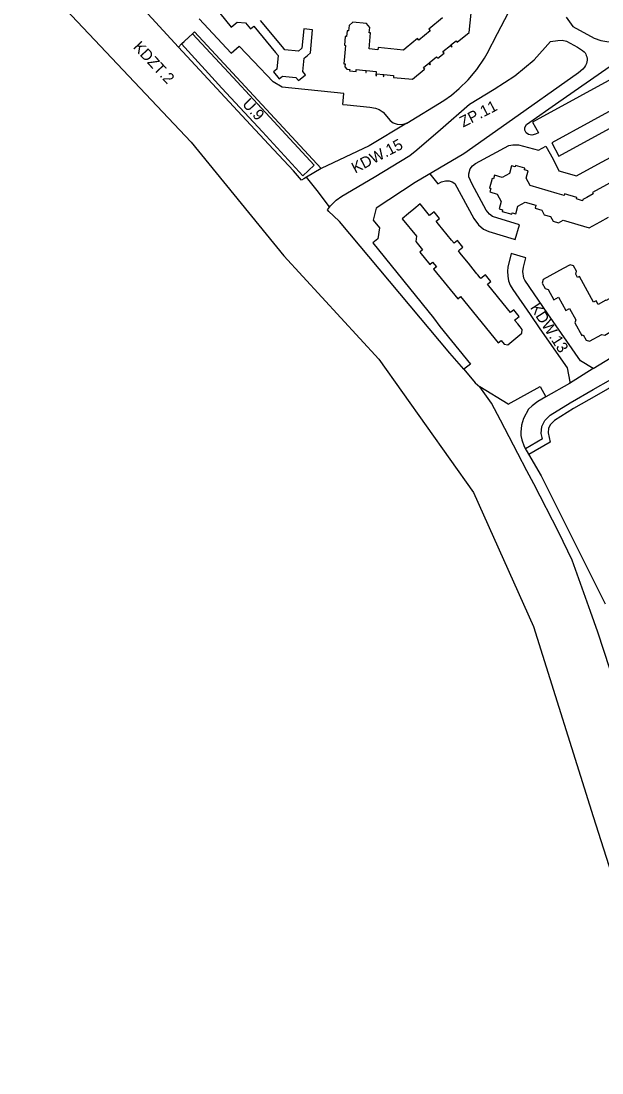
# Model space of a CAD drawing. Extents: x 7426178 to 7427732, y 5548847 to 5550287.
# Drawn here: x 7426699.7 to 7426935.7, y 5549279.8 to 5549707.1 of the extents above; entities that cross this region are included whole.
import ezdxf

# ---------------------------------------------------------------- set-up
doc = ezdxf.new("R2010")
doc.units = 0
for name, color, linetype in [('linie_rozgraniczajace', 7, 'Continuous'), ('linie_zabudowy_nieprzekraczalne', 7, 'Continuous'), ('linie_zabudowy_obowiazujace', 7, 'Continuous'), ('oznaczenia_przeznaczen', 7, 'Continuous')]:
    doc.layers.add(name, color=color, linetype=linetype)

msp = doc.modelspace()

# ---------------------------------------------------------------- linework, layer by layer
at = {"layer": 'linie_rozgraniczajace'}
for p, q in [((7426932.15, 5549565.9), (7426922.5, 5549559.91)), ((7426884.2, 5549560.11), (7426886.06, 5549558.53)), ((7426897.6, 5549551.53), (7426886.06, 5549558.53)), ((7426901.49, 5549531.49), (7426894.43, 5549544.99)), ((7426911.56, 5549537.38), (7426904.58, 5549533.3))]:
    msp.add_line(p, q, dxfattribs=at)
for points in [[(7426376.27, 5550136.98), (7426418.26, 5550074.28), (7426423.32, 5550066.18), (7426432.5, 5550051.32), (7426442.7, 5550038.38), (7426480.49, 5549982.45), (7426537.39, 5549902.3), (7426546.67, 5549891.59), (7426553.32, 5549883.92), (7426562.25, 5549871.78), (7426591.41, 5549843), (7426644.02, 5549790.07), (7426768.78, 5549657.84), (7426806.41, 5549611.72)], [(7426810.33, 5549646.2), (7426800.44, 5549656.88), (7426791.22, 5549666.83), (7426763.7, 5549696.53), (7426746.59, 5549715), (7426724.9, 5549738.06), (7426706.19, 5549757.95)], [(7426921.19, 5549708.68), (7426923.92, 5549704.82), (7426932.51, 5549700.17), (7426935.18, 5549699.15), (7426937.7, 5549698.72), (7426940.53, 5549698.67), (7426942.25, 5549698.99), (7426944.97, 5549699.87), (7426946.33, 5549700.48), (7426947.4, 5549701.24), (7426955.49, 5549706.64), (7426958.19, 5549707.88), (7426961.05, 5549708.75), (7426963.27, 5549709.23), (7426965.77, 5549709.6), (7426974.88, 5549710.13), (7426996.27, 5549711.61), (7427000.22, 5549712.16), (7427006.34, 5549713.7), (7427091.63, 5549747.86), (7427113.84, 5549707.59), (7427113.65, 5549702.41), (7427125.67, 5549680.75), (7427127, 5549680.04)], [(7426889.1, 5549693.95), (7426893.27, 5549702.02), (7426902.25, 5549719.14)], [(7426772.11, 5549707.95), (7426785.12, 5549693.98), (7426788.38, 5549696.87)], [(7426763.7, 5549696.53), (7426764.94, 5549697.75), (7426766.01, 5549698.76), (7426769.45, 5549701.97), (7426770.19, 5549702.65), (7426821.62, 5549647.18), (7426815.68, 5549643.69), (7426814.56, 5549643.04), (7426813.58, 5549642.48)], [(7426914.79, 5549698.8), (7426917.74, 5549699.2), (7426919.47, 5549699.28), (7426921.22, 5549698.93), (7426925.81, 5549696.44), (7426927.82, 5549695.15), (7426928.41, 5549694.63), (7426928.81, 5549694.12), (7426929.08, 5549693.66), (7426929.33, 5549693.03), (7426929.5, 5549692.47), (7426929.67, 5549691.91), (7426929.62, 5549691.19), (7426929.57, 5549690.49), (7426929.41, 5549689.78), (7426929.05, 5549689.04), (7426928.63, 5549688.35), (7426927.96, 5549687.56), (7426926.13, 5549686.04), (7426896.99, 5549665.4), (7426879.58, 5549653.14), (7426859.82, 5549641.56), (7426844.02, 5549631.06), (7426842.79, 5549626.24), (7426845.34, 5549623.14), (7426844.65, 5549618.61), (7426842.65, 5549616.98), (7426867.3, 5549586.48), (7426869.83, 5549582.97), (7426882.23, 5549567.76), (7426879.56, 5549565.69), (7426884.2, 5549560.11)], [(7426802.18, 5549682.43), (7426794.17, 5549690.79), (7426788.38, 5549696.87)], [(7426879.56, 5549565.69), (7426873.94, 5549572.19), (7426829.14, 5549625.63), (7426826.68, 5549627.91), (7426824.71, 5549629.72), (7426824.15, 5549630.36), (7426825.38, 5549632.06), (7426827.74, 5549634.28), (7426830.06, 5549635.9), (7426843.16, 5549643.7), (7426857.6, 5549652.43), (7426860.55, 5549654.73), (7426870.08, 5549663.09), (7426881.88, 5549673.34), (7426891.96, 5549679.36), (7426900.35, 5549684.81), (7426908.09, 5549691.28), (7426914.79, 5549698.8)], [(7426871.41, 5549674.74), (7426874.57, 5549677.02), (7426877.72, 5549679.65), (7426881.33, 5549683.25), (7426884.86, 5549687.46), (7426887.93, 5549692.01), (7426889.1, 5549693.95)], [(7426830.37, 5549673.21), (7426830.81, 5549677.61), (7426805.78, 5549680.15), (7426802.18, 5549682.43)], [(7426849.66, 5549666.68), (7426850.81, 5549665.74), (7426852.44, 5549665.25), (7426854.22, 5549665.09), (7426856.43, 5549665.63), (7426871.41, 5549674.74)], [(7426830.37, 5549673.21), (7426832.14, 5549673.01), (7426841.42, 5549672.16), (7426843.75, 5549671.69), (7426845.24, 5549671.14), (7426846.82, 5549670.11), (7426849.66, 5549666.68)], [(7426856.43, 5549665.63), (7426841.11, 5549656.34), (7426821.62, 5549647.18)], [(7426865.76, 5549645.04), (7426869.05, 5549640.99), (7426870.55, 5549641.83), (7426872.2, 5549642.22), (7426873.59, 5549642.16), (7426874.89, 5549641.77), (7426875.93, 5549641.1), (7426883.66, 5549626.91), (7426885.48, 5549624.35), (7426887.62, 5549622.57), (7426889.73, 5549621.59), (7426900, 5549618.51), (7426900.46, 5549618.35), (7426902.13, 5549624.24), (7426891.21, 5549627.63), (7426890.05, 5549628.57), (7426888.71, 5549630.2), (7426882.99, 5549640.88), (7426881.67, 5549643.74), (7426881.58, 5549644.99), (7426882.19, 5549647.11), (7426883.08, 5549648.21), (7426884.33, 5549649.16), (7426897.91, 5549656.55), (7426899.49, 5549656.86), (7426901.81, 5549656.76), (7426909.87, 5549654.57), (7426912.9, 5549656.26), (7426915.84, 5549651), (7426918.12, 5549646.19), (7426925.31, 5549644.17), (7426934.07, 5549648.97), (7426965.67, 5549666.05)], [(7426813.58, 5549642.48), (7426810.33, 5549646.2)], [(7426825.05, 5549631.61), (7426819.94, 5549638.19), (7426815.68, 5549643.69)], [(7426806.41, 5549611.72), (7426845.02, 5549569.73), (7426883.5, 5549515.53), (7426907.93, 5549461.17), (7426932.17, 5549384.03), (7426948.93, 5549331.51), (7426962.26, 5549289.73), (7427024.27, 5549067.18), (7427061.13, 5549001.37), (7427073.43, 5548973.27), (7427176.69, 5548896.63), (7427213.08, 5548849.03)], [(7426932.15, 5549565.9), (7426926.98, 5549569.13), (7426913.7, 5549588.22), (7426904.31, 5549601.79), (7426903.92, 5549602.7), (7426903.5, 5549605.35), (7426903.76, 5549607.11), (7426904.81, 5549610.9), (7426898.83, 5549612.62), (7426897.45, 5549607.09), (7426897.32, 5549605.53), (7426897.48, 5549603.52), (7426897.78, 5549601.57), (7426898.37, 5549599.85), (7426899.43, 5549598.05), (7426906.54, 5549587.93), (7426910.4, 5549582.02), (7426921.61, 5549566.16), (7426922.58, 5549560.57)], [(7426932.15, 5549565.9), (7426941.86, 5549571.96), (7426967.18, 5549586.1), (7426997, 5549602.57)], [(7426911.56, 5549537.38), (7426911.05, 5549539.62), (7426911.32, 5549542.39), (7426912.47, 5549544.85), (7426914.67, 5549546.95), (7426922.71, 5549552.03), (7426932.12, 5549557.37), (7426946.41, 5549565.6)], [(7426894.43, 5549544.99), (7426890.85, 5549551.84), (7426886.06, 5549558.53)], [(7426897.6, 5549551.53), (7426910.58, 5549558.63), (7426912.86, 5549554.47)], [(7426922.58, 5549560.57), (7426922.5, 5549559.91), (7426912.86, 5549554.47), (7426909.67, 5549552.53), (7426907.35, 5549550.78), (7426905.89, 5549549.42), (7426903.87, 5549545.6), (7426902.97, 5549542.93), (7426902.69, 5549540.15), (7426902.78, 5549538.71), (7426903.12, 5549536.97), (7426904.11, 5549534.22), (7426904.88, 5549532.73)], [(7426904.88, 5549532.73), (7426911.01, 5549522.31), (7426916.04, 5549512.37), (7426937.03, 5549470.34)], [(7426931, 5549467.22), (7426923.61, 5549488.06), (7426918.22, 5549499.32), (7426907.98, 5549519.12), (7426905.19, 5549524.43), (7426901.49, 5549531.49)], [(7426992.18, 5549317.21), (7426991, 5549317.16), (7426989.83, 5549317.1), (7426988.88, 5549317.26), (7426987.93, 5549317.42), (7426985.16, 5549318.25), (7426982.53, 5549319.42), (7426980.83, 5549320.24), (7426979.12, 5549321.06), (7426977.93, 5549321.54), (7426977.13, 5549324.09), (7426969.55, 5549344.6), (7426966.16, 5549355.3), (7426964.77, 5549360.68), (7426963.54, 5549369.01), (7426959.75, 5549382.4), (7426957.29, 5549390.35), (7426953.68, 5549396.84), (7426950.49, 5549408.37), (7426938.9, 5549444.02), (7426933.99, 5549458.8), (7426931, 5549467.22)]]:
    msp.add_lwpolyline(points, dxfattribs=at)
for points in [[(7426909.9, 5549661.64), (7426908.7, 5549661.09), (7426907.17, 5549660.78), (7426905.84, 5549660.95), (7426904.88, 5549661.62), (7426904.36, 5549662.8), (7426904.38, 5549663.77), (7426905.1, 5549665.03), (7426918.22, 5549674.28), (7426959.43, 5549702.93), (7426961.6, 5549703.49), (7426964.15, 5549703.68), (7426966.39, 5549703.42), (7426967.87, 5549702.82), (7426969.25, 5549701.93), (7426970.04, 5549700.89), (7426970.63, 5549699.48), (7426970.63, 5549697.16), (7426969.89, 5549695.21), (7426968.73, 5549693.98), (7426967.09, 5549692.91), (7426964.77, 5549697.22), (7426907.49, 5549665.94)], [(7426915.26, 5549657.59), (7426918.14, 5549652.2), (7426983.18, 5549687.7), (7426991.34, 5549694.79), (7426999.55, 5549699.32), (7427000.52, 5549700.08), (7427002.33, 5549702.14), (7427002.85, 5549702.91), (7427003.13, 5549704.1), (7427002.83, 5549705.21), (7427002.12, 5549706.15), (7427001.44, 5549706.64), (7427000.79, 5549706.81), (7426981.34, 5549705.51), (7426979.64, 5549704.94), (7426978.1, 5549704.02), (7426977, 5549702.63), (7426976.19, 5549699.99), (7426976.18, 5549697.79), (7426976.42, 5549696.42), (7426977.37, 5549694.34), (7426978.74, 5549692.27)]]:
    msp.add_lwpolyline(points, close=True, dxfattribs=at)
at = {"layer": 'linie_zabudowy_nieprzekraczalne'}
msp.add_lwpolyline([(7426947.78, 5549563.22), (7426933.48, 5549554.99), (7426924.12, 5549549.68), (7426916.37, 5549544.78), (7426914.74, 5549543.22), (7426914, 5549541.66), (7426913.82, 5549539.8), (7426914.67, 5549536.07), (7426905.95, 5549530.97)], dxfattribs=at)
at = {"layer": 'linie_zabudowy_obowiazujace'}
for p, q in [((7426794.22, 5549704.99), (7426803.02, 5549694.31)), ((7426805.86, 5549696.65), (7426797.05, 5549707.34)), ((7426816.09, 5549693.13), (7426817.24, 5549694.1)), ((7426863.49, 5549687.42), (7426863.7, 5549687.59)), ((7426802.36, 5549666.3), (7426785.87, 5549684.09)), ((7426781.27, 5549679.83), (7426797.76, 5549662.04)), ((7426901.57, 5549631.82), (7426904.55, 5549633.47)), ((7426904.55, 5549633.47), (7426908.83, 5549632.23)), ((7426908.83, 5549632.23), (7426908.5, 5549631.08)), ((7426908.5, 5549631.08), (7426911.23, 5549630.29)), ((7426911.23, 5549630.29), (7426912.25, 5549628.43)), ((7426912.25, 5549628.43), (7426914.77, 5549627.7)), ((7426914.77, 5549627.7), (7426915.83, 5549625.82)), ((7426935, 5549625.57), (7426938.36, 5549627.42)), ((7426930.54, 5549623.12), (7426935, 5549625.57)), ((7426933.35, 5549593.42), (7426932.3, 5549592.84)), ((7426934.17, 5549591.95), (7426933.35, 5549593.42))]:
    msp.add_line(p, q, dxfattribs=at)
for points in [[(7426794.32, 5549721.62), (7426792.15, 5549719.83), (7426788.82, 5549720.15), (7426786.82, 5549722.64), (7426781.2, 5549718.03), (7426783.23, 5549715.55), (7426782.9, 5549712.24), (7426780.44, 5549710.21), (7426785.04, 5549704.65), (7426787.5, 5549706.64), (7426790.83, 5549706.33), (7426792.86, 5549703.86), (7426794.22, 5549704.99)], [(7426863.7, 5549687.59), (7426863.19, 5549688.2), (7426865.31, 5549689.95), (7426865.82, 5549689.34), (7426866.01, 5549689.5), (7426865.51, 5549690.1), (7426868.5, 5549692.56), (7426869, 5549691.95), (7426871.57, 5549694.07), (7426871.08, 5549694.68), (7426874.12, 5549697.19), (7426874.62, 5549696.58), (7426874.82, 5549696.74), (7426874.32, 5549697.35), (7426876.44, 5549699.1), (7426876.94, 5549698.49), (7426881.75, 5549702.44), (7426883.04, 5549715.7)], [(7426870.9, 5549708.36), (7426865.34, 5549703.76), (7426865.9, 5549703.09), (7426861.31, 5549699.29), (7426860.74, 5549699.99), (7426856.2, 5549696.23)], [(7426817.24, 5549694.1), (7426818.16, 5549703.55), (7426814.56, 5549703.9), (7426813.8, 5549696.05), (7426813.71, 5549695.97)], [(7426856.2, 5549696.23), (7426855.08, 5549695.3), (7426844.74, 5549696.31), (7426844.65, 5549695.43), (7426841.1, 5549695.77), (7426841.73, 5549702.22), (7426841.14, 5549702.28), (7426841.36, 5549704.49), (7426840.08, 5549706.02), (7426834.46, 5549706.55), (7426832.94, 5549705.3), (7426832.73, 5549703.1), (7426832.14, 5549703.16), (7426831.91, 5549700.75), (7426831.41, 5549700.8), (7426831.07, 5549697.21), (7426831.55, 5549697.17), (7426830.83, 5549689.69), (7426831.41, 5549689.64), (7426831.3, 5549688.52), (7426832.1, 5549687.55), (7426833.22, 5549687.44), (7426833.16, 5549686.85), (7426835.8, 5549686.58), (7426835.88, 5549687.38), (7426839.81, 5549686.97), (7426839.73, 5549686.21), (7426839.96, 5549686.19), (7426840.04, 5549686.97), (7426843.98, 5549686.57), (7426843.81, 5549684.9), (7426844.06, 5549684.88), (7426844.14, 5549685.68), (7426846.89, 5549685.39), (7426846.81, 5549684.62), (7426847.05, 5549684.59), (7426847.14, 5549685.38), (7426851.06, 5549684.97), (7426850.98, 5549684.21), (7426858.68, 5549683.42), (7426863.49, 5549687.42)], [(7426785.87, 5549684.09), (7426769.39, 5549701.87), (7426764.94, 5549697.75), (7426781.27, 5549679.83)], [(7426813.71, 5549695.97), (7426812.39, 5549694.87), (7426806.92, 5549695.36), (7426805.86, 5549696.65)], [(7426803.02, 5549694.31), (7426804.11, 5549693.1), (7426803.56, 5549687.55), (7426802.23, 5549686.48), (7426804.55, 5549683.66), (7426805.89, 5549684.73), (7426811.36, 5549684.19), (7426812.43, 5549682.88), (7426815.3, 5549685.21), (7426814.19, 5549686.56), (7426814.73, 5549691.98), (7426816.09, 5549693.13)], [(7426797.76, 5549662.04), (7426814.25, 5549644.25), (7426818.84, 5549648.52), (7426802.36, 5549666.3)], [(7426917.49, 5549637.08), (7426906.52, 5549640.27), (7426904.87, 5549643.25), (7426905.75, 5549646.27), (7426904.25, 5549646.7), (7426904.41, 5549647.27), (7426900.56, 5549648.4), (7426900.39, 5549647.82), (7426898.95, 5549648.24), (7426898.07, 5549645.22), (7426895.09, 5549643.59), (7426892.07, 5549644.46), (7426891.66, 5549643.01), (7426891.08, 5549643.18), (7426889.95, 5549639.26), (7426890.52, 5549639.1), (7426890.11, 5549637.65), (7426893.12, 5549636.79), (7426894.77, 5549633.8), (7426893.89, 5549630.78), (7426895.33, 5549630.36), (7426895.16, 5549629.78), (7426899.08, 5549628.65), (7426899.25, 5549629.22), (7426900.69, 5549628.8), (7426901.57, 5549631.82)], [(7426970.12, 5549634.75), (7426968.8, 5549637.16), (7426969.15, 5549638.38), (7426966.55, 5549643.12), (7426965.32, 5549643.47), (7426964.72, 5549644.58), (7426963.49, 5549644.93), (7426962.88, 5549646.05), (7426956.11, 5549648.01), (7426954.99, 5549647.4), (7426953.77, 5549647.75), (7426952.66, 5549647.14), (7426951.43, 5549647.49), (7426943.56, 5549643.16), (7426943.27, 5549643.68), (7426931.81, 5549637.38), (7426932.1, 5549636.85), (7426929.56, 5549635.46)], [(7426929.56, 5549635.46), (7426927.9, 5549634.55), (7426927.77, 5549634.1), (7426925.35, 5549634.81), (7426925.52, 5549635.38), (7426920.45, 5549636.86), (7426920.28, 5549636.27), (7426917.49, 5549637.08)], [(7426859.3, 5549630.66), (7426857.13, 5549628.9), (7426854.53, 5549626.79), (7426860.29, 5549619.69), (7426860.07, 5549617.58), (7426862.82, 5549614.2), (7426861.65, 5549613.25), (7426865.75, 5549608.21), (7426866.92, 5549609.16), (7426868.49, 5549607.22), (7426867.32, 5549606.26), (7426877.1, 5549594.24), (7426878.25, 5549595.18), (7426893.56, 5549576.35), (7426894.73, 5549577.29), (7426895.96, 5549575.78), (7426897.43, 5549575.62), (7426903.18, 5549580.29), (7426903.34, 5549581.77), (7426902.45, 5549582.85), (7426901.46, 5549584.08), (7426900.21, 5549585.61), (7426900.68, 5549585.99), (7426902.07, 5549587.12), (7426899.87, 5549589.84), (7426898.47, 5549588.71), (7426897.32, 5549590.13), (7426889.16, 5549600.17), (7426890.56, 5549601.3), (7426888.35, 5549604.02), (7426886.49, 5549602.51), (7426886.27, 5549602.78), (7426885.26, 5549604.02), (7426884.91, 5549604.45), (7426884.38, 5549605.11), (7426883.37, 5549606.35), (7426882.45, 5549607.48), (7426881.45, 5549608.72), (7426878.69, 5549612.11), (7426877.67, 5549613.36), (7426877.35, 5549613.76), (7426877.82, 5549614.14), (7426879.21, 5549615.28), (7426877, 5549617.99), (7426875.61, 5549616.86), (7426874.61, 5549618.09), (7426869.3, 5549624.62), (7426868.36, 5549625.78), (7426869.75, 5549626.92), (7426867.55, 5549629.63), (7426866.15, 5549628.5), (7426865.69, 5549628.12), (7426861.9, 5549632.78), (7426859.3, 5549630.66)], [(7426915.83, 5549625.82), (7426918.05, 5549625.18), (7426919.9, 5549626.21), (7426930.54, 5549623.12)], [(7426922.72, 5549608.12), (7426919.87, 5549606.55), (7426911.76, 5549602.09), (7426911.36, 5549600.67), (7426912.61, 5549598.4), (7426913.84, 5549598.05), (7426916.17, 5549593.8), (7426918.1, 5549594.86), (7426921.03, 5549589.52), (7426922.52, 5549590.34), (7426925.03, 5549585.77), (7426924.69, 5549584.55), (7426927.52, 5549579.39), (7426928.04, 5549579.68), (7426929.27, 5549577.44), (7426930.69, 5549577.03), (7426935.68, 5549579.78), (7426936.89, 5549579.44), (7426942.59, 5549582.82), (7426941.49, 5549584.68), (7426944.16, 5549586.15), (7426946.2, 5549585.56), (7426950.15, 5549587.74)], [(7426925.39, 5549605.43), (7426924.14, 5549607.7), (7426922.72, 5549608.12)], [(7426932.3, 5549592.84), (7426926.52, 5549603.36), (7426925.73, 5549602.92), (7426925.03, 5549604.2), (7426925.39, 5549605.43)], [(7426944.72, 5549597.62), (7426937.39, 5549593.56), (7426937.32, 5549593.69), (7426934.17, 5549591.95)]]:
    msp.add_lwpolyline(points, dxfattribs=at)

# ---------------------------------------------------------------- texts
at = {"layer": 'oznaczenia_przeznaczen'}
for s, rotation, p in [('KDZT.2', 313.2672, (7426744.98, 5549696.26)), ('U.9', 313.4071, (7426789.29, 5549673.09)), ('ZP.11', 27.0441, (7426879.32, 5549663.77)), ('KDW.15', 27.6185, (7426835.43, 5549645.1)), ('KDW.13', 303.0477, (7426906.35, 5549590.68))]:
    msp.add_text(s, height=4.5, rotation=rotation, dxfattribs=at).set_placement(p)

doc.saveas('drawing.dxf')
